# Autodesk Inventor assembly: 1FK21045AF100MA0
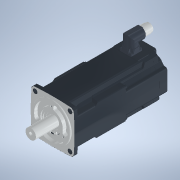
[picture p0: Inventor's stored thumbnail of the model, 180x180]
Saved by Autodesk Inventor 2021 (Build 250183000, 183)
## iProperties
Category: PARTsolutions
Created: 2026-06
Part Number: 1FK21045AF100MA0
Catalog Web Link: www.3dfindit.com
Description: 1FK21045AF100MA0-Servo synchronous motor
Document SubType Name: Assembly
Designer: psAdmin
Mass: 961.159 g
Surface Area: 1195.26 cm^2
Volume: 961.159 cm^3
Density: 1 g/cm^3
Title: 1FK21045AF100MA0
Author: Cadenas PARTsolutions
Comments: Servo synchronous motor
PSOL_IDENT_0: {$CADENAS_DATA/23d-libs/siemens_ag/_cat_/52/6b/1fk21045af100ma0.prj},193 {STYP=ASS},{VTYP=3D},{NB=1F
PSOL_IDENT_1: K21045AF100MA0},{LINA=1FK21045AF100MA0},{NN=1FK21045AF100MA0},{DATE=19.08.2025 14:00:38},{GEOMDATE=3
PSOL_IDENT_2: 0.07.2025 02:01:45},{VERSION=},{LINEID=10},{WBVAR=},{WBNUMERIC=}  {NB=1FK21045AF100MA0},{LINA=1FK210
PSOL_IDENT_3: 45AF100MA0},{KT=DUMMY},{PREVIEW=../../../_pool_/cb/72/p_d211_xx_00434j.png},{DESCSHORT=SIMOTICS S-1F
PSOL_IDENT_4: K2 HD, SINAMICS S210 3AC 400V-480V, 2.4 Nm, 3000 rpm},{DESCLONG=SIMOTICS S-1FK2 HD servo motor M0=2.
PSOL_IDENT_5: 4 Nm; PN = 0.75 kW at nN=3000 rpm (380-480 V); PN = 0.375 kW at nN=1500 rpm (200-240 V); with holdin
PSOL_IDENT_6: g brake; degree of protection IP64; cylindrical shaft D19x40mm; absolute encoder 22-bit + 12-bit mul
PSOL_IDENT_7: titurn (encoder AM22DQC); with OCC interface; plug size M17, rotatable; SIMOTICS S-1FK2 servomotorfo
PSOL_IDENT_8: r a wide range of uses in industrial environments. SIMOTICS S‑1FK2 servomotors are compact synchrono
PSOL_IDENT_9: us motors with a high dynamic performance that set themselves apart as a result of their high power
PSOL_IDENT_10: density, degree of protection and overload capability. The motors are available in two variants: as
PSOL_IDENT_11: High Dynamic variant (highest dynamic performance as a result of the low intrinsic moment of inertia
PSOL_IDENT_12: for applications demanding a high dynamic performance with low moved masses) - and as Compact varia
PSOL_IDENT_13: nt (precise and stable closed-loop control for medium up to large moved masses as a result of a medi
PSOL_IDENT_14: um intrinsic moment of inertia). SIMOTICSS‑1FK2 servomotors fully exploit their strengths in a syste
PSOL_IDENT_15: m with the SINAMICSS210 frequency converter and simple connection using the one cable connection (OC
PSOL_IDENT_16: C). Advantages include the short control and positioning times, fast and precise correction of distu
PSOL_IDENT_17: rbing quantities as well as stable control with a high dynamic performance. The servo motors can be
PSOL_IDENT_18: configured to address a wide range of requirements. For example with and without holding brake, IP64
PSOL_IDENT_19: or IP65 degree of protection, singleturn or multiturn absolute encoders - to name just a few. Furth
PSOL_IDENT_20: er, the servomotors are available in different shaft heights extending from 20 to 100. A shaft seali
PSOL_IDENT_21: ng ring is available to achieve an IP65 degree of protection and for subsequent mounting at the moto
PSOL_IDENT_22: r or as spare part. SIMOTICS - the optimum motor for each and every motion control application.},{IN
PSOL_IDENT_23: TNO=804766906411},{SUPPLIERALTNO=1FK2104-5AF10-0MA0},{MANUID=1FK21045AF100MA0},{MANUNAME=Siemens},{M
PSOL_IDENT_24: ANUTYPEDESC=Synchronous motor 1FK2-HD 2.4 NM},{AAU732=SIMOTICS},{AAO057=S-1FK2},{AAU734=SIMOTICS S-1
PSOL_IDENT_25: FK2 HD servo motor M0=2.4 Nm; PN = 0.75 kW at nN=3000 rpm (380-480 V); PN = 0.375 kW at nN=1500 rpm
PSOL_IDENT_26: (200-240 V); with holding brake; degree of protection IP64; cylindrical shaft D19x40mm; absolute enc
PSOL_IDENT_27: oder 22-bit + 12-bit multiturn (encoder AM22DQC); with OCC interface; plug size M17, rotatable;},{AA
PSOL_IDENT_28: W338=Synchronous motor 1FK2-HD 2.4 NM},{AAO742=SIMOTICS},{AAO663=4042948693070},{NOCUPEROU=1},{PRICE
PSOL_IDENT_29: QUANTITY=1},{QUANTITYMIN=1},{QUANTITYINT=1},{CTN=85015100},{COO=DE},{AAO676=1FK2104-5AF10-0MA0},{AAO
PSOL_IDENT_30: 677=Siemens AG},{ORDERUNIT=C62},{CONTENTUNIT=C62}
NB: 1FK21045AF100MA0
NN: 1FK21045AF100MA0
NT: Servo synchronous motor
NBSYN: $MANUID.
LINA: 1FK21045AF100MA0
CATALOG: SIEMENS
PREVIEW: ../../../_pool_/cb/72/p_d211_xx_00434j.png
DESCSHORT: SIMOTICS S-1FK2 HD, SINAMICS S210 3AC 400V-480V, 2.4 Nm, 3000 rpm
DESCLONG: SIMOTICS S-1FK2 HD servo motor M0=2.4 Nm; PN = 0.75 kW at nN=3000 rpm (380-480 V); PN = 0.375 kW at nN=1500 rpm (200-240 V); with holding brake; degree of prote
INTNO: 804766906411
SUPPLIERALTNO: 1FK2104-5AF10-0MA0
MANUID: 1FK21045AF100MA0
MANUNAME: Siemens
MANUTYPEDESC: Synchronous motor 1FK2-HD 2.4 NM
AAU732: SIMOTICS
AAO057: S-1FK2
AAU734: SIMOTICS S-1FK2 HD servo motor M0=2.4 Nm; PN = 0.75 kW at nN=3000 rpm (380-480 V); PN = 0.375 kW at nN=1500 rpm (200-240 V); with holding brake; degree of prote
AAW338: Synchronous motor 1FK2-HD 2.4 NM
AAO742: SIMOTICS
AAO663: 4042948693070.0
NOCUPEROU: 1
PRICEQUANTITY: 1
QUANTITYMIN: 1
QUANTITYINT: 1
CTN: 85015100
COO: DE
ARTICLENO: 1FK21045AF100MA0
BOMINFO: 1FK21045AF100MA0
CREATOR: CADENAS GmbH
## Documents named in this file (24)
- e:\temp\worker_COMMON_12\temp\tmp_2820_10_ZXgEO\format_0\1FK21045AF100MA0.iam
- e:\temp\worker_COMMON_12\temp\tmp_2820_10_ZXgEO\format_0\1FK21045AF100MA0_PART1.ipt
- e:\temp\worker_COMMON_12\temp\tmp_2820_10_ZXgEO\format_0\1FK21045AF100MA0_PART2.ipt
- e:\temp\worker_COMMON_12\temp\tmp_2820_10_ZXgEO\format_0\1FK21045AF100MA0_PART3.ipt
- e:\temp\worker_COMMON_12\temp\tmp_2820_10_ZXgEO\format_0\1FK21045AF100MA0_PART4.ipt
- e:\temp\worker_COMMON_12\temp\tmp_2820_10_ZXgEO\format_0\1FK21045AF100MA0_PART5.ipt
- e:\temp\worker_COMMON_12\temp\tmp_2820_10_ZXgEO\format_0\1FK21045AF100MA0_PART6.ipt
- e:\temp\worker_COMMON_12\temp\tmp_2820_10_ZXgEO\format_0\1FK21045AF100MA0_PART7.ipt
- e:\temp\worker_COMMON_12\temp\tmp_2820_10_ZXgEO\format_0\1FK21045AF100MA0_PART8.ipt
- e:\temp\worker_COMMON_12\temp\tmp_2820_10_ZXgEO\format_0\1FK21045AF100MA0_PART9.ipt
- e:\temp\worker_COMMON_12\temp\tmp_2820_10_ZXgEO\format_0\1FK21045AF100MA0_PART10.ipt
- e:\temp\worker_COMMON_12\temp\tmp_2820_10_ZXgEO\format_0\1FK21045AF100MA0_PART11.ipt
- e:\temp\worker_COMMON_12\temp\tmp_2820_10_ZXgEO\format_0\1FK21045AF100MA0_PART12.ipt
- e:\temp\worker_COMMON_12\temp\tmp_2820_10_ZXgEO\format_0\1FK21045AF100MA0_PART13.ipt
- e:\temp\worker_COMMON_12\temp\tmp_2820_10_ZXgEO\format_0\1FK21045AF100MA0_PART14.ipt
- e:\temp\worker_COMMON_12\temp\tmp_2820_10_ZXgEO\format_0\1FK21045AF100MA0_PART15.ipt
- e:\temp\worker_COMMON_12\temp\tmp_2820_10_ZXgEO\format_0\1FK21045AF100MA0_PART16.ipt
- e:\temp\worker_COMMON_12\temp\tmp_2820_10_ZXgEO\format_0\1FK21045AF100MA0_PART17.ipt
- e:\temp\worker_COMMON_12\temp\tmp_2820_10_ZXgEO\format_0\1FK21045AF100MA0_PART18.ipt
- e:\temp\worker_COMMON_12\temp\tmp_2820_10_ZXgEO\format_0\1FK21045AF100MA0_PART19.ipt
- e:\temp\worker_COMMON_12\temp\tmp_2820_10_ZXgEO\format_0\1FK21045AF100MA0_PART20.ipt
- e:\temp\worker_COMMON_12\temp\tmp_2820_10_ZXgEO\format_0\1FK21045AF100MA0_PART21.ipt
- e:\temp\worker_COMMON_12\temp\tmp_2820_10_ZXgEO\format_0\1FK21045AF100MA0_PART22.ipt
- e:\temp\worker_COMMON_12\temp\tmp_2820_10_ZXgEO\format_0\1FK21045AF100MA0_PART23.ipt
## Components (23 placed, 23 different names)
1. 1FK21045AF100MA0_PART1:1
2. 1FK21045AF100MA0_PART2:1
3. 1FK21045AF100MA0_PART3:1
4. 1FK21045AF100MA0_PART4:1
5. 1FK21045AF100MA0_PART5:1
6. 1FK21045AF100MA0_PART6:1
7. 1FK21045AF100MA0_PART7:1
8. 1FK21045AF100MA0_PART8:1
9. 1FK21045AF100MA0_PART9:1
10. 1FK21045AF100MA0_PART10:1
11. 1FK21045AF100MA0_PART11:1
12. 1FK21045AF100MA0_PART12:1
13. 1FK21045AF100MA0_PART13:1
14. 1FK21045AF100MA0_PART14:1
15. 1FK21045AF100MA0_PART15:1
16. 1FK21045AF100MA0_PART16:1
17. 1FK21045AF100MA0_PART17:1
18. 1FK21045AF100MA0_PART18:1
19. 1FK21045AF100MA0_PART19:1
20. 1FK21045AF100MA0_PART20:1
21. 1FK21045AF100MA0_PART21:1
22. 1FK21045AF100MA0_PART22:1
23. 1FK21045AF100MA0_PART23:1
